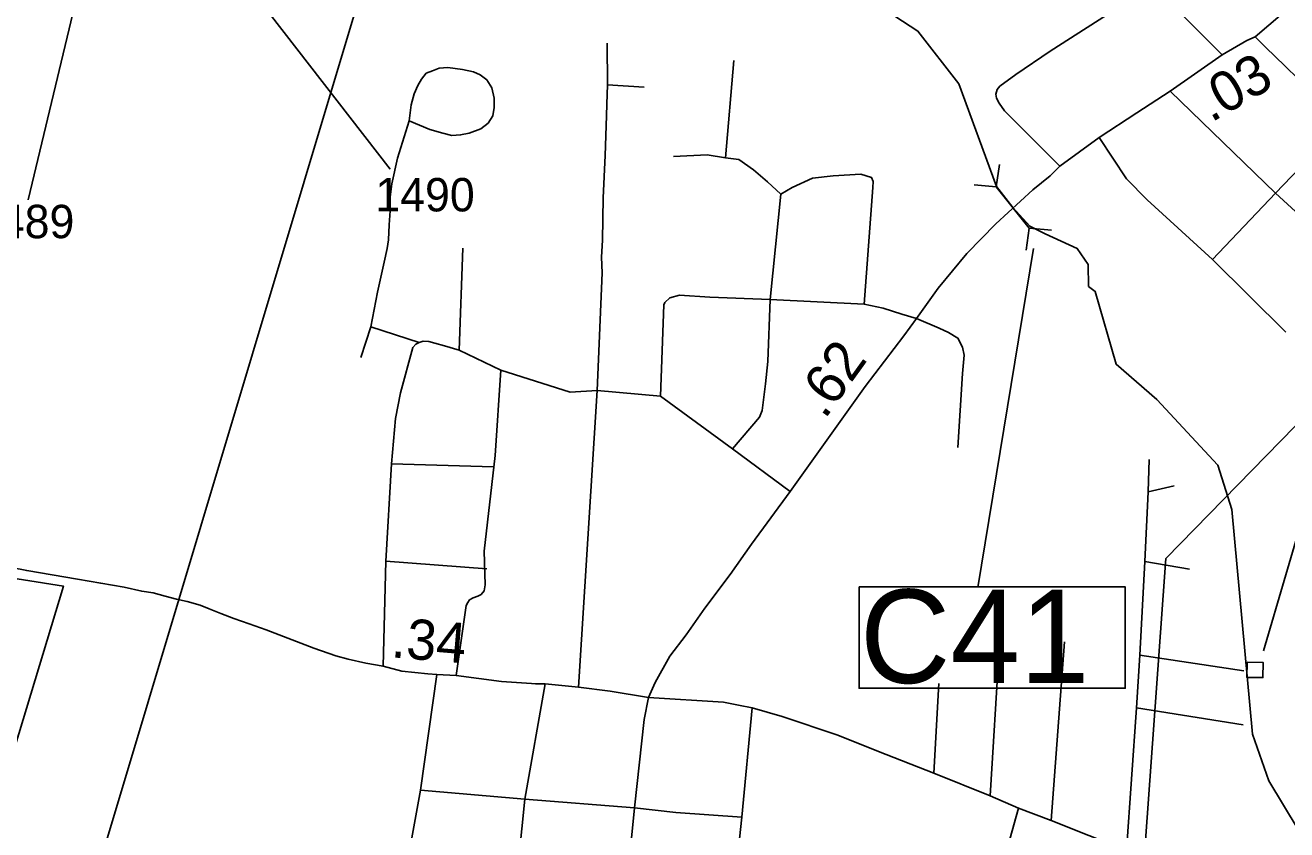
# Model space of a CAD drawing. Extents: x 2290615 to 2522933, y 819489 to 1012715.
# Drawn here: x 2389226 to 2393947, y 981982 to 984993 of the extents above; entities that cross this region are included whole.
import ezdxf

# ---------------------------------------------------------------- set-up
doc = ezdxf.new("R2010")
doc.units = 0
for name, color, linetype in [('Exist Boundary Political City Limit New', 7, 'Continuous'), ('Exist Boundary Political City Limit Old', 7, 'Continuous'), ('Exist Hydrographic Creek Single Shore', 7, 'Continuous'), ('Exist Hydrographic Creek Single Shore Label', 7, 'Continuous'), ('Exist Road Non-System Structure Non-Sys Other Number Label', 7, 'Continuous'), ('Exist Road Non-System Type 51', 7, 'Continuous'), ('Exist Road Primary NC Attributed', 7, 'Continuous'), ('Exist Road Primary NC Mileage Hundredths English Label', 7, 'Continuous'), ('Exist Road Primary NC Structure Culvert CELL', 7, 'Continuous'), ('Exist Road Primary NC Structure Culvert Number Label', 7, 'Continuous'), ('Exist Road Primary US Attributed', 7, 'Continuous'), ('Exist Road Primary US Mileage Hundredths English Label', 7, 'Continuous'), ('Exist Road Secondary Type 51 Attributed', 7, 'Continuous'), ('Exist Road Secondary Type 51 Number Label', 7, 'Continuous'), ('Exist Utilities Electrical Transmission Line', 7, 'Continuous'), ('Map Preparation Boundary City Limit Buffer Line', 7, 'Continuous')]:
    doc.layers.add(name, color=color, linetype=linetype)

msp = doc.modelspace()

# ---------------------------------------------------------------- linework, layer by layer
at = {"layer": 'Exist Boundary Political City Limit New'}
msp.add_lwpolyline([(2390853.6, 986356.8), (2389493.5, 981816), (2389078.7, 981936.4), (2389369.2, 982893.4), (2388943.6, 982960.5), (2388694.8, 981544.7), (2388565.3, 980833.1), (2388622.3, 980658.4), (2388645.5, 980577.3), (2388704.6, 980503.6), (2388847.4, 980382.6), (2388912.3, 980324.6), (2389037.7, 980322.3), (2389279, 980347.8), (2389265.1, 980612.1), (2389279, 980723.4), (2389336.9, 980814.4), (2393618.8, 980687.8), (2394515, 980647.9)], dxfattribs=at)
at = {"layer": 'Exist Boundary Political City Limit Old'}
msp.add_lwpolyline([(2390853.6, 986356.8), (2389493.5, 981816), (2389078.7, 981936.4), (2389369.2, 982893.4), (2388943.6, 982960.5), (2388694.8, 981544.7), (2388565.3, 980833.1), (2388622.3, 980658.4), (2388645.5, 980577.3), (2388704.6, 980503.6), (2388847.4, 980382.6), (2388912.3, 980324.6), (2389037.7, 980322.3), (2389279, 980347.8), (2389265.1, 980612.1), (2389279, 980723.4), (2389316.4, 980858.1), (2393618.8, 980687.8), (2394515, 980647.9)], dxfattribs=at)
at = {"layer": 'Exist Hydrographic Creek Single Shore'}
msp.add_lwpolyline([(2392390.4, 985084.9), (2392566.6, 984970.6), (2392719.5, 984773.3), (2392860.4, 984389.2), (2392921.6, 984310.9), (2392985.5, 984240.5), (2393042.8, 984211.8), (2393162.8, 984157), (2393203.5, 984097.2), (2393204.5, 984015.2), (2393229.5, 983996.6), (2393308.5, 983724), (2393460.6, 983592.4), (2393688.6, 983345.7), (2393740.5, 983180.3), (2393818.6, 982339.8), (2393879.5, 982165.1), (2393989.6, 981982.5)], dxfattribs=at)
at = {"layer": 'Exist Hydrographic Creek Single Shore Label'}
msp.add_lwpolyline([(2393798.1, 982609), (2393858.2, 982608), (2393857.2, 982551), (2393797.1, 982552)], close=True, dxfattribs=at)
at = {"layer": 'Exist Road Non-System Structure Non-Sys Other Number Label'}
msp.add_lwpolyline([(2393859.8, 982650.9), (2394026.5, 983219.6), (2394634.5, 984474.8), (2394879.7, 984906.3)], dxfattribs=at)
at = {"layer": 'Exist Road Non-System Type 51'}
for p, q in [((2391405.1, 984770), (2391403.9, 984925.6)), ((2391846.5, 984496.1), (2391877.6, 984860.4)), ((2391846.5, 984496.1), (2391877.6, 984860.4)), ((2391405.1, 984770), (2391542.3, 984760.9)), ((2393904.4, 984364.2), (2393510.1, 984746.6)), ((2393904.4, 984364.2), (2393510.1, 984746.6)), ((2393904.4, 984364.2), (2394157.9, 984628.5)), ((2393904.4, 984364.2), (2394157.9, 984628.5)), ((2392013.7, 983966.1), (2392054.2, 984360.9)), ((2392013.7, 983966.1), (2392054.2, 984360.9)), ((2393668.5, 984115.8), (2393904.4, 984364.2)), ((2393668.5, 984115.8), (2393904.4, 984364.2)), ((2393904.4, 984364.2), (2394254.7, 984041.8)), ((2393904.4, 984364.2), (2394254.7, 984041.8)), ((2390863.2, 984159), (2390849.5, 983776.9)), ((2390863.2, 984159), (2390849.5, 983776.9)), ((2393668.5, 984115.8), (2393943.1, 983844.5)), ((2393668.5, 984115.8), (2393943.1, 983844.5)), ((2392013.7, 983966.1), (2392365.8, 983948.5)), ((2392013.7, 983966.1), (2392365.8, 983948.5)), ((2390482.5, 983749.4), (2390519.1, 983863.8)), ((2390519.1, 983863.8), (2390700.6, 983805.7)), ((2390849.5, 983776.9), (2391005.5, 983701.4)), ((2390849.5, 983776.9), (2391005.5, 983701.4)), ((2391296.4, 982515.3), (2391365.9, 983626.1)), ((2391296.4, 982515.3), (2391365.9, 983626.1)), ((2391365.9, 983626.1), (2391603.5, 983604.9)), ((2391365.9, 983626.1), (2391603.5, 983604.9)), ((2391603.5, 983604.9), (2391872.9, 983407.6)), ((2391603.5, 983604.9), (2391872.9, 983407.6)), ((2391872.9, 983407.6), (2392088.5, 983248.2)), ((2391872.9, 983407.6), (2392088.5, 983248.2)), ((2390576.2, 982987.4), (2390596.8, 983351.3)), ((2390576.2, 982987.4), (2390596.8, 983351.3)), ((2390596.8, 983351.3), (2390978.7, 983339.8)), ((2390596.8, 983351.3), (2390978.7, 983339.8)), ((2393428.2, 983246.4), (2393431.7, 983368)), ((2393428.2, 983246.4), (2393431.7, 983368)), ((2393428.2, 983246.4), (2393525, 983269.3)), ((2393428.2, 983246.4), (2393525, 983269.3)), ((2393415.9, 982985.7), (2393428.2, 983246.4)), ((2393415.9, 982985.7), (2393428.2, 983246.4)), ((2390566.3, 982593.9), (2390576.2, 982987.4)), ((2390566.3, 982593.9), (2390576.2, 982987.4)), ((2390576.2, 982987.4), (2390953.5, 982957.7)), ((2390576.2, 982987.4), (2390953.5, 982957.7)), ((2393396.5, 982635.1), (2393415.9, 982985.7)), ((2393396.5, 982635.1), (2393415.9, 982985.7)), ((2393415.9, 982985.7), (2393583.1, 982957.5)), ((2393415.9, 982985.7), (2393583.1, 982957.5)), ((2392836.7, 982108.3), (2392870.2, 982658)), ((2392836.7, 982108.3), (2392870.2, 982658)), ((2393065.6, 982016.7), (2393114.9, 982684.4)), ((2393065.6, 982016.7), (2393114.9, 982684.4)), ((2393384.2, 982437.7), (2393396.5, 982635.1)), ((2393384.2, 982437.7), (2393396.5, 982635.1)), ((2393396.5, 982635.1), (2393785.6, 982576.9)), ((2393396.5, 982635.1), (2393785.6, 982576.9)), ((2390704.9, 982129.4), (2390766.5, 982562.8)), ((2390704.9, 982129.4), (2390766.5, 982562.8)), ((2391095.7, 982096), (2391171.4, 982527.6)), ((2391095.7, 982096), (2391171.4, 982527.6)), ((2392625.5, 982192.9), (2392644.8, 982529.4)), ((2392625.5, 982192.9), (2392644.8, 982529.4)), ((2391907.2, 982029), (2391945.9, 982437.7)), ((2391907.2, 982029), (2391945.9, 982437.7)), ((2393347.2, 981903.9), (2393384.2, 982437.7)), ((2393347.2, 981903.9), (2393384.2, 982437.7)), ((2393384.2, 982437.7), (2393783.8, 982374.3)), ((2393384.2, 982437.7), (2393783.8, 982374.3)), ((2390704.9, 982129.4), (2391095.7, 982096)), ((2390704.9, 982129.4), (2391095.7, 982096)), ((2391000.6, 981179.8), (2391095.7, 982096)), ((2391000.6, 981179.8), (2391095.7, 982096))]:
    msp.add_line(p, q, dxfattribs=at)
for points in [[(2393098.1, 984464.7), (2392890.7, 984672.8), (2392871, 984700.7), (2392861, 984719.7), (2392858.7, 984734.2), (2392863.3, 984751.7), (2392872.8, 984764.2), (2392932.7, 984808.2), (2393061.2, 984896.3), (2393444.9, 985143)], [(2390663.1, 984635), (2390740.9, 984603), (2390788.9, 984589.2), (2390823.2, 984580.1), (2390855.2, 984582.4), (2390887.2, 984589.2), (2390930.6, 984605.2), (2390958.1, 984625.8), (2390976.4, 984653.3), (2390980.9, 984685.3), (2390980.9, 984719.7), (2390971.8, 984758.6), (2390953.5, 984788.3), (2390928.3, 984806.6), (2390903.2, 984818.1), (2390862, 984827.2), (2390807.2, 984834.1), (2390775.2, 984831.8), (2390750, 984822.6), (2390727.1, 984813.5), (2390708.8, 984790.6), (2390695.1, 984767.7), (2390681.4, 984735.7), (2390670, 984694.5), (2390663.1, 984635)], [(2391365.9, 983626.1), (2391385.3, 984066.5), (2391382.2, 984124.7), (2391386.8, 984188.8), (2391389.5, 984346.6), (2391395.9, 984504.6), (2391401.7, 984653.3), (2391402.8, 984696.8), (2391405.1, 984770)], [(2391365.9, 983626.1), (2391385.3, 984066.5), (2391382.2, 984124.7), (2391386.8, 984188.8), (2391389.5, 984346.6), (2391395.9, 984504.6), (2391401.7, 984653.3), (2391402.8, 984696.8), (2391405.1, 984770)], [(2390519.1, 983863.8), (2390544.2, 983994.3), (2390569.4, 984106.4), (2390581.3, 984157), (2390585.9, 984189), (2390588.8, 984246), (2390592.2, 984298.6), (2390592.2, 984349), (2390598, 984399.3), (2390619.7, 984495.4), (2390663.1, 984635)], [(2393244.2, 984572.1), (2393347.5, 984417.6), (2393423.8, 984339.6), (2393668.5, 984115.8)], [(2393244.2, 984572.1), (2393347.5, 984417.6), (2393423.8, 984339.6), (2393668.5, 984115.8)], [(2391652.4, 984501.5), (2391778.2, 984507.3), (2391846.5, 984496.1)], [(2391652.4, 984501.5), (2391778.2, 984507.3), (2391846.5, 984496.1)], [(2391846.5, 984496.1), (2391896.6, 984490.8), (2391951, 984451.6), (2392003.5, 984406.3), (2392054.2, 984360.9)], [(2391846.5, 984496.1), (2391896.6, 984490.8), (2391951, 984451.6), (2392003.5, 984406.3), (2392054.2, 984360.9)], [(2392365.8, 983948.5), (2392397.8, 984385.5), (2392399.5, 984407.6), (2392393.3, 984423.3), (2392353.2, 984434.9), (2392249.3, 984429.4), (2392171.5, 984420.4), (2392095.8, 984385.5), (2392054.2, 984360.9)], [(2392365.8, 983948.5), (2392397.8, 984385.5), (2392399.5, 984407.6), (2392393.3, 984423.3), (2392353.2, 984434.9), (2392249.3, 984429.4), (2392171.5, 984420.4), (2392095.8, 984385.5), (2392054.2, 984360.9)], [(2391603.5, 983604.9), (2391615.9, 983946.7), (2391619.4, 983955.5), (2391638.8, 983973.1), (2391674, 983981.9), (2391788.4, 983974.9), (2392013.7, 983966.1)], [(2391603.5, 983604.9), (2391615.9, 983946.7), (2391619.4, 983955.5), (2391638.8, 983973.1), (2391674, 983981.9), (2391788.4, 983974.9), (2392013.7, 983966.1)], [(2391872.9, 983407.6), (2391973.2, 983525.6), (2391983.8, 983550.3), (2391996.1, 983650.7), (2392004.6, 983734.3), (2392013.7, 983966.1)], [(2391872.9, 983407.6), (2391973.2, 983525.6), (2391983.8, 983550.3), (2391996.1, 983650.7), (2392004.6, 983734.3), (2392013.7, 983966.1)], [(2392365.8, 983948.5), (2392436.2, 983934.4), (2392506.6, 983911.5), (2392561.2, 983895.6), (2392645.7, 983858.6), (2392680.9, 983842.8), (2392716.1, 983821.6), (2392733.7, 983788.1), (2392739, 983758.2), (2392733.7, 983689.5), (2392716.1, 983412.9)], [(2390596.8, 983351.3), (2390611.7, 983520.6), (2390630, 983616.7), (2390676.3, 983786), (2390687.4, 983798.6), (2390700.6, 983805.7)], [(2390700.6, 983805.7), (2390714.8, 983810.6), (2390736.6, 983809.5), (2390758.6, 983803.2), (2390794.6, 983792.9), (2390849.5, 983776.9)], [(2391005.5, 983701.4), (2390985.4, 983382.8), (2390944.1, 983024.3), (2390947.9, 982898.4), (2390944.2, 982876.4), (2390932.4, 982862.3), (2390920.4, 982856), (2390902.5, 982849.9), (2390888.6, 982841.7), (2390882.8, 982831.6), (2390876.8, 982821.4), (2390838.7, 982559.3)], [(2391005.5, 983701.4), (2391265.6, 983619), (2391365.9, 983626.1)], [(2391005.5, 983701.4), (2391265.6, 983619), (2391365.9, 983626.1)], [(2391000.6, 981179.8), (2390666.1, 981190.4), (2390618.6, 981195.7), (2390592.2, 981201), (2390572.8, 981213.3), (2390558.8, 981264.4), (2390569.3, 981368.3), (2390597.5, 981533.9), (2390704.9, 982129.4)], [(2391000.6, 981179.8), (2390666.1, 981190.4), (2390618.6, 981195.7), (2390592.2, 981201), (2390572.8, 981213.3), (2390558.8, 981264.4), (2390569.3, 981368.3), (2390597.5, 981533.9), (2390704.9, 982129.4)], [(2391095.7, 982096), (2391505.8, 982064.2), (2391660.8, 982045.7), (2391907.2, 982029)], [(2391544, 980612.3), (2391602.8, 980630.8), (2391671.2, 980682.3), (2391730.1, 980758.9), (2391769.8, 980847.5), (2391788.4, 980920.2), (2391798.1, 981015.1), (2391826.2, 981274.1), (2391907.2, 982029)], [(2392942.3, 982062.5), (2392910.6, 981946.2), (2392900.1, 981875.7), (2392907.1, 981851.1), (2392917.7, 981824.6), (2392933.5, 981798.2), (2392965.2, 981763), (2393044.4, 981717.2), (2393164.1, 981671.4), (2393299.7, 981616.7), (2393438.8, 981567.4)]]:
    msp.add_lwpolyline(points, dxfattribs=at)
at = {"layer": 'Exist Road Primary NC Attributed'}
for points in [[(2393828.7, 984949.2), (2393931.1, 985036.5)], [(2393705.5, 984882.2), (2393797, 984935.1), (2393828.7, 984949.2)], [(2391558.7, 982476.5), (2391583.3, 982532.9), (2391637.9, 982631.5), (2391699.5, 982710.8), (2391769.9, 982811.2), (2391864.1, 982937.2), (2391944.2, 983050), (2392088.5, 983248.2), (2392369.3, 983640.2), (2392513.7, 983830.4), (2392561.2, 983895.6), (2392642.2, 984008.4), (2392749.6, 984138.7), (2392858.7, 984249.7), (2392996, 984376.6), (2393061.2, 984429.4), (2393098.1, 984464.7), (2393244.2, 984572.1), (2393385.1, 984665.5), (2393510.1, 984746.6), (2393705.5, 984882.2)], [(2391431, 981151.6), (2391433.7, 981271.4), (2391437.2, 981400), (2391472.4, 981722.5), (2391505.8, 982064.2), (2391542.8, 982393.7), (2391558.7, 982476.5)]]:
    msp.add_lwpolyline(points, dxfattribs=at)
at = {"layer": 'Exist Road Primary NC Structure Culvert CELL'}
for p, q in [((2392871.4, 984471), (2392859.8, 984388.5)), ((2392776.8, 984395.6), (2392859.8, 984388.5)), ((2392859.8, 984388.5), (2392983.4, 984233.4)), ((2392971.8, 984150.9), (2392983.4, 984233.4)), ((2393066.4, 984226.3), (2392983.4, 984233.4))]:
    msp.add_line(p, q, dxfattribs=at)
at = {"layer": 'Exist Road Primary NC Structure Culvert Number Label'}
msp.add_line((2392998.5, 984156.6), (2392790.6, 982888.7), dxfattribs=at)
msp.add_lwpolyline([(2392346.5, 982890.8), (2393342, 982890.8), (2393342, 982511), (2392346.5, 982511)], close=True, dxfattribs=at)
at = {"layer": 'Exist Road Primary US Attributed'}
for points in [[(2388982.5, 983000.1), (2389232, 982951.5), (2389421.8, 982919.6), (2389509.1, 982904.5), (2389596.5, 982889.4), (2389662.7, 982874.5), (2389704.7, 982867.8), (2389750, 982856), (2389792, 982844.3), (2389832.3, 982835.9), (2389881, 982822.4), (2389914.6, 982809), (2389958.3, 982790.5), (2390007, 982772), (2390064.1, 982751.8), (2390127.9, 982730), (2390305.9, 982661.1), (2390388.2, 982632.5), (2390435.3, 982620.7), (2390500.8, 982605.6), (2390566.3, 982593.9), (2390635.8, 982575.7), (2390733.2, 982565.6), (2390766.5, 982562.8), (2390838.7, 982559.3), (2391008.7, 982537), (2391121.2, 982528.6), (2391136.2, 982527.6), (2391171.4, 982527.6), (2391296.4, 982515.3), (2391415.1, 982500), (2391558.7, 982476.5)], [(2391558.7, 982476.5), (2391838.6, 982458.9), (2391894.9, 982448.3), (2391945.9, 982437.7), (2392058.6, 982406), (2392266.3, 982335.6), (2392419.5, 982273.9), (2392625.5, 982192.9), (2392836.7, 982108.3), (2392942.3, 982062.5), (2393065.6, 982016.7), (2393347.2, 981903.9), (2393877.1, 981681.9), (2394220.4, 981548)]]:
    msp.add_lwpolyline(points, dxfattribs=at)
at = {"layer": 'Exist Road Secondary Type 51 Attributed'}
for points in [[(2393705.5, 984882.2), (2393444.9, 985143), (2393121, 985460.1), (2392872.8, 985705), (2392682.7, 985891.7), (2392513.7, 986062.6), (2392358.8, 986217.6), (2392251.4, 986314.5), (2392047.2, 986515.4), (2391851.8, 986705.7), (2391593, 986962.9), (2391263.8, 987288.8), (2391083.8, 987467.3)], [(2393828.7, 984949.2), (2393870.9, 984906.9), (2393900.9, 984878.7), (2394157.9, 984628.5)]]:
    msp.add_lwpolyline(points, dxfattribs=at)
at = {"layer": 'Exist Road Secondary Type 51 Number Label'}
for p, q in [((2389552.9, 985658.2), (2389237.5, 984339.4)), ((2389803.7, 985471.8), (2390592.2, 984454))]:
    msp.add_line(p, q, dxfattribs=at)
at = {"layer": 'Exist Utilities Electrical Transmission Line'}
msp.add_lwpolyline([(2400210.1, 988342.6), (2399851.9, 988057.9), (2398657.7, 987180.1), (2397606.3, 986390.4), (2394192.6, 983711.4), (2393494.2, 982996.3), (2393414.9, 981889.3), (2393365.6, 981228.6), (2393332.4, 980716.4), (2393280.6, 980253.7), (2393248.6, 979805.3), (2393212.7, 979350.8), (2393157.4, 978842.2), (2393091.8, 978355.4)], dxfattribs=at)
at = {"layer": 'Map Preparation Boundary City Limit Buffer Line'}
msp.add_lwpolyline([(2390853.6, 986356.8), (2389493.5, 981816), (2389078.7, 981936.4), (2389369.2, 982893.4), (2388943.6, 982960.5), (2388694.8, 981544.7), (2388565.3, 980833.1), (2388622.3, 980658.4), (2388645.5, 980577.3), (2388704.6, 980503.6), (2388847.4, 980382.6), (2388912.3, 980324.6), (2389037.7, 980322.3), (2389279, 980347.8), (2389265.1, 980612.1), (2389279, 980723.4), (2389336.9, 980814.4), (2393618.8, 980687.8), (2394515, 980647.9)], dxfattribs=at)

# ---------------------------------------------------------------- texts
at = {"layer": 'Exist Road Primary NC Mileage Hundredths English Label'}
for s, rotation, p in [('.03', 30.001, (2393663.7, 984627.1)), ('.62', 54.3863, (2392218, 983514.8))]:
    msp.add_text(s, height=150, rotation=rotation, dxfattribs=at).set_placement(p)
at = {"layer": 'Exist Road Primary NC Structure Culvert Number Label'}
msp.add_text('C41', height=350, dxfattribs=at).set_placement((2392349.8, 982530.8))
at = {"layer": 'Exist Road Primary US Mileage Hundredths English Label'}
msp.add_text('.34', height=150, rotation=355.2827, dxfattribs=at).set_placement((2390592.7, 982627.3))
at = {"layer": 'Exist Road Secondary Type 51 Number Label'}
for s, p in [('1490', (2390536.4, 984296)), ('1489', (2389038.4, 984195.6))]:
    msp.add_text(s, height=125, dxfattribs=at).set_placement(p)

doc.saveas('drawing.dxf')
